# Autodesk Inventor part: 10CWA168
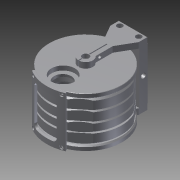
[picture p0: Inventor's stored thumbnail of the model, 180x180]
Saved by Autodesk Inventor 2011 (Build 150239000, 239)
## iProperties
Created: 2011-04
Part Number: 10CWA168
Document SubType Name: Modeling
Designer: vadybininkas6
Density: 1 g/cm^3
Author: vadybininkas6
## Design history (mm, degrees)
feature "Base1"
body "Solid1"
